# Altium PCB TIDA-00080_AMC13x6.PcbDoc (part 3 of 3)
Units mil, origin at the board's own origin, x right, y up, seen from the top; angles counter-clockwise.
Board outline 7283.46 x 2559.06 mil, 4 copper layers (Top Layer, MidLayer1, MidLayer2, Bottom Layer), stack 61.2 mil thick; 372 components, 160 nets, 901 pads, 256 vias.
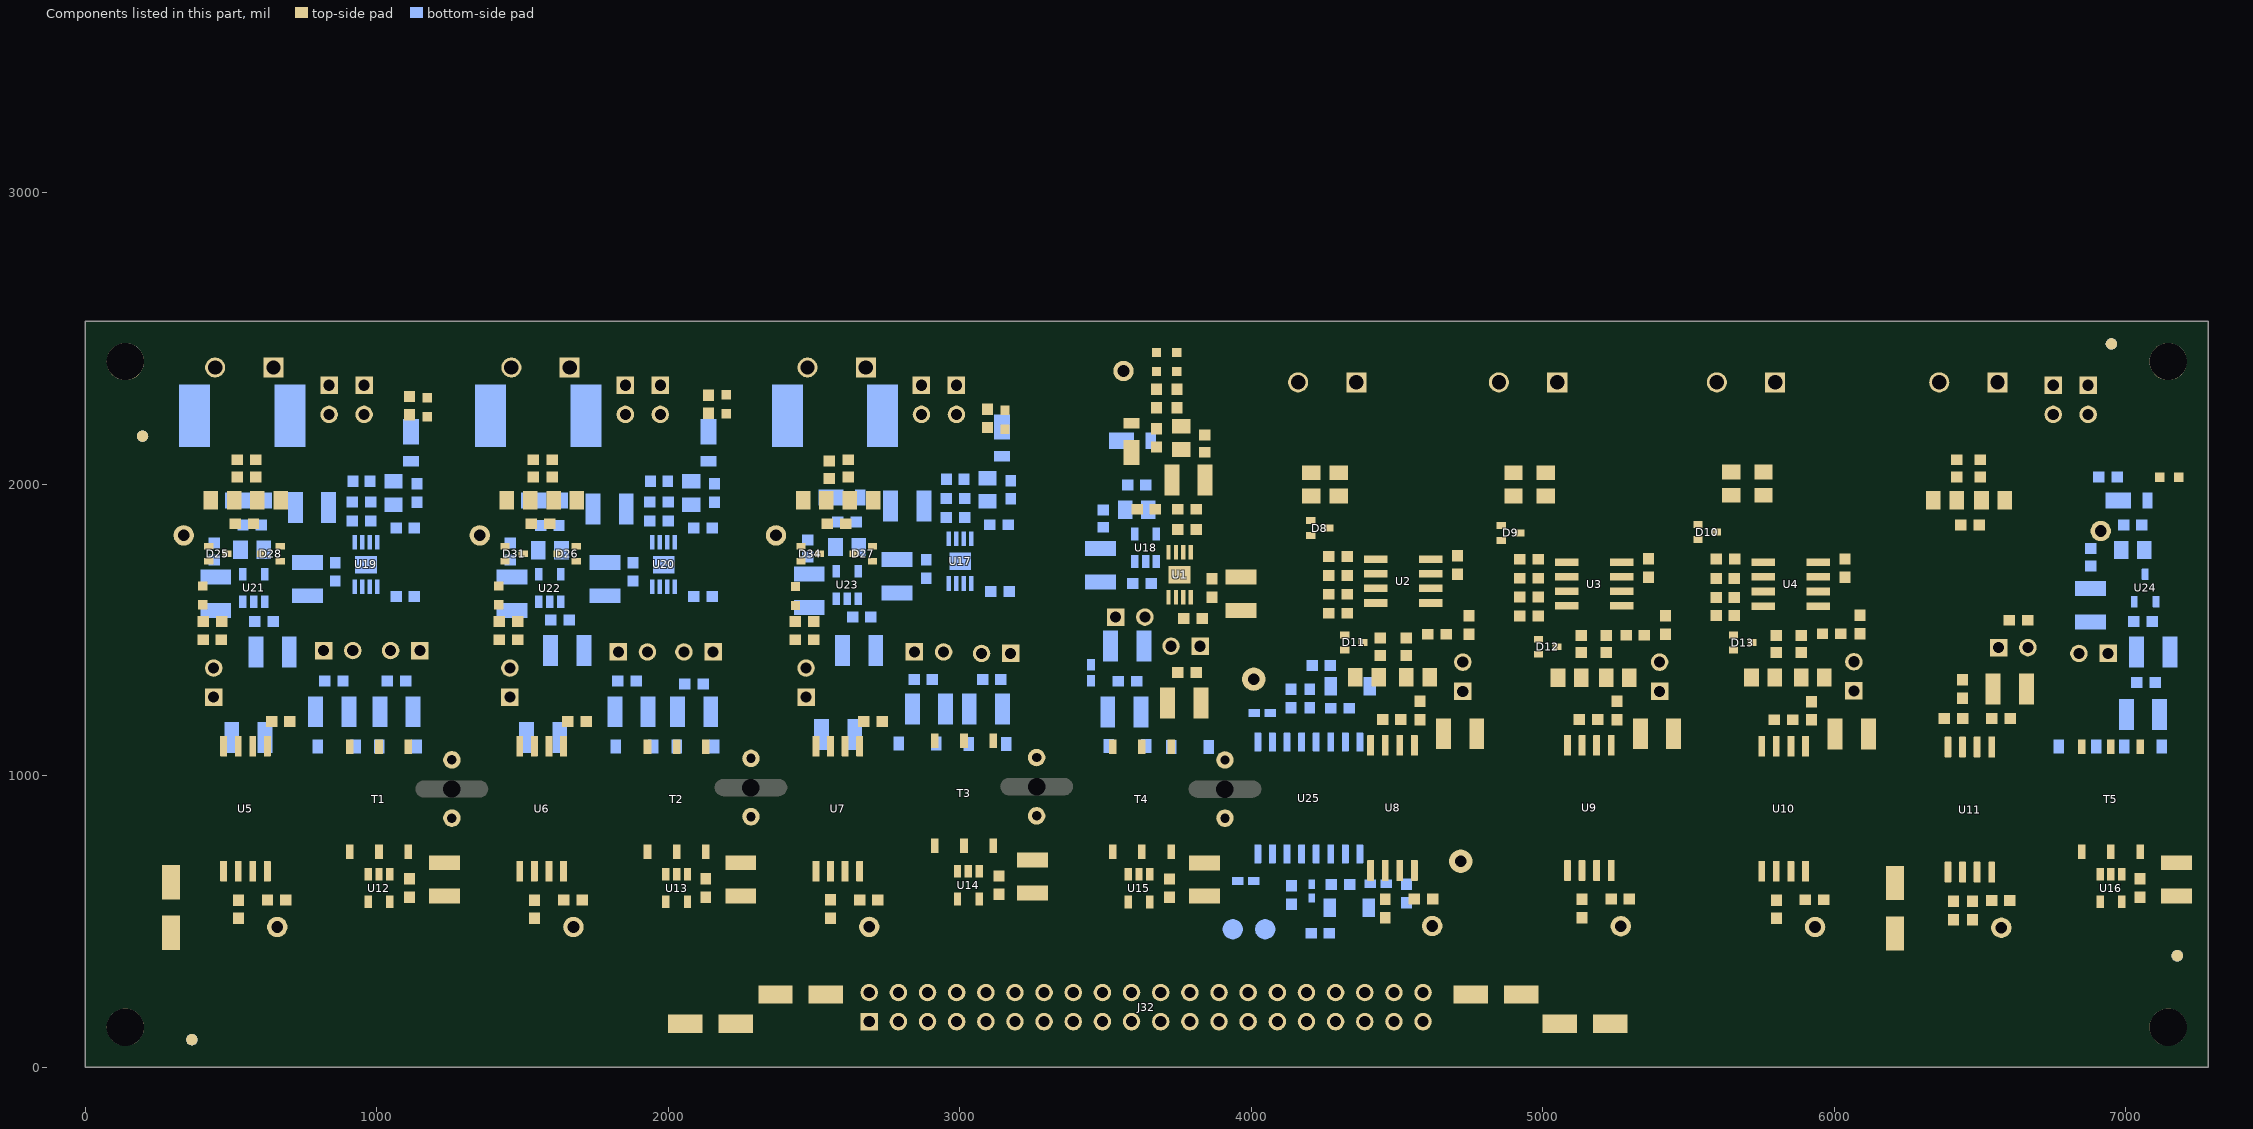
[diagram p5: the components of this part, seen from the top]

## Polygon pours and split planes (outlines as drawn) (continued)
GND_WSH1 on MidLayer2 "g" (solid, remove dead copper, pour order 193): 3214,2500 2851,2500 2841,2490 2838,2487 2838,2366 2838,2101 2817,2080 2362,2080 2338,2056 2328,2046 2328,1815 2328,1311 2420,1219 2434.99,1204.01 2434.99,1170 2434.99,1079 2443.99,1070 3100,1070 3245,1215 3245,2469
-5.0V_PH on MidLayer2 "g" (solid, remove dead copper, pour order 191): 6190,1095 6158.5,1063.5 3552.99,1063.5 3475.2,1141.3 3430.2,1186.3 3430.2,1844.72 3430.2,2476.2 3454,2500 3802,2500 3813,2489 3832,2470 3832,2370 3832,2290 3856,2266 4125,1997 6155,1997 6190.17,1961.84
+5.0V_VDC on MidLayer2 "g" (solid, remove dead copper, pour order 183): 6340,1997 7169,1997 7215,1951 7215,1095 7183.5,1063.5 6360.5,1063.5 6330,1094 6306.45,1117.55 6306.45,1905 6306.45,1963.45
DGND on MidLayer2 "g" (solid, remove dead copper, pour order 177): 45,554.53 45,762 67,784 7211,784 7234,761 7234,92 7188,46 93,46 46,93 45,94 45,550.05
+5.0V_PH on Bottom Layer "g" (solid, remove dead copper, pour order 179): 3582,2330 3792,2330 3856,2266 4125,1997 6155,1997 6190,1962 6190,1137 6190,1095 6165,1070 6158.5,1063.5 6020.5,1063.5 4234.5,1063.5 4114,1184 4038,1260 4038,1560 4038,1802 3737,2103 3737,2147 3737,2183 3710,2210 3614,2210 3597,2193 3597,1884 3592,1879 3541.08,1879 3527.6,1892.48 3467.6,1892.48 3457.6,1902.48 3457.6,2292.6 3495,2330
+5V_CNTL on Bottom Layer "g" (solid, remove dead copper, pour order 175): 45,554.53 45,762 67,784 7211,784 7234,761 7234,92 7188,46 93,46 46,93 45,94 45,550.05
NetC134_1 on Bottom Layer "vdd" (solid, remove dead copper, pour order 229): 3444,1350 3565.6,1350 3567.6,1348 3567.6,1301.6 3543,1277 3543,1082 3529,1068 3488.89,1068 3472.89,1084 3472.89,1143.61 3430.2,1186.3 3430.2,1347.17 3433,1349.97
+6V_PH on Bottom Layer "vdd" (solid, remove dead copper, pour order 227): 3446,1577 3430.2,1561.2 3430.2,1361.82 3433,1359.02 3469.02,1359.02 3488.84,1378.84 3561.84,1378.84 3569,1386 3569,1572 3564,1577
GND_XSH1 on Bottom Layer "g" (solid, remove dead copper, pour order 213): 6780,2370 6724,2370 6721,2367 6721,2047 6671,1997 6340,1997 6322,1979 6306.45,1963.45 6306.45,1117.55 6360.5,1063.5 6728.21,1063.5 6744.58,1079.87 6744.58,1625.58 6791,1672 6800,1681 6800,2232 6800,2359 6789,2370
GND_VDC on Bottom Layer "g" (solid, remove dead copper, pour order 181): 6836,2365 6836,2219 6970,2085 7049,2006 7049,1735.45 7054.45,1730 7089.45,1730 7099.45,1720 7099.45,1660 7084.45,1645 7059.45,1645 7054.45,1640 7054.45,1575 7069.45,1560 7069.45,1510 7094.45,1485 7094.45,1152.55 7103,1144 7214,1144 7227,1157 7236,1166 7236,2078 7100,2214 6944,2370 6841,2370
NetC48_1 on Bottom Layer "g" (solid, remove dead copper, pour order 161): 2601.99,1265 2561.99,1305 2441.99,1305 2434.99,1298 2434.99,1230 2439.99,1225 2550.99,1225 2599.99,1176 2599.99,1077 2606.99,1070 2689.99,1070 2694.99,1075 2694.99,1246 2694.99,1259 2688.99,1265
GND_WSH1 on Bottom Layer "g" (solid, remove dead copper, pour order 163): 2564.99,1184 2564.99,1079 2558.99,1073 2555.99,1070 2549.99,1070 2443.99,1070 2434.99,1079 2434.99,1188 2441.99,1195 2558.99,1195 2564.99,1189
-6V_WSH on Bottom Layer "g" (solid, remove dead copper, pour order 159): 2953,1700 2862,1700 2832,1670 2742,1670 2727,1655 2727,1595 2807,1515 3112,1515 3137,1490 3137,1395 3112,1370 3112,1095 3127,1080 3172,1080 3197,1105 3197,1360 3222,1385 3222,1525 3182,1565 2993,1565 2967,1591 2967,1685 2965.1,1686.9 2952,1700 2948.3,1700
-6V_VSH on Bottom Layer "g" (solid, remove dead copper, pour order 157): 1940,1690 1849,1690 1819,1660 1729,1660 1714,1645 1714,1585 1794,1505 2099,1505 2124,1480 2124,1385 2099,1360 2099,1085 2114,1070 2169,1070 2184,1085 2184,1350 2209,1375 2209,1515 2169,1555 1980,1555 1954,1581 1954,1675 1952.1,1676.9 1939,1690 1935.3,1690
-6V_USH on Bottom Layer "g" (solid, remove dead copper, pour order 155): 919,1690 828,1690 798,1660 708,1660 693,1645 693,1585 773,1505 1078,1505 1103,1480 1103,1385 1078,1360 1078,1085 1093,1070 1148,1070 1163,1085 1163,1350 1188,1375 1188,1515 1148,1555 959,1555 933,1581 933,1675 931.1,1676.9 918,1690 914.3,1690
NetC91_2 on Bottom Layer "g" (solid, remove dead copper, pour order 153): 2975.4,1787 2948.4,1787 2935.4,1800 2875.4,1800 2850.4,1825 2850.4,1976 2861.4,1987 2921.4,1987 2929.4,1995 2929.4,2037 2937.4,2045 2976.4,2045 2979.4,2042 2979.4,1864 2975.4,1860
-5.0V_WSH on Bottom Layer "g" (solid, remove dead copper, pour order 151): 2995.39,1990.78 2995.39,2095.78 3010.39,2110.78 3080.39,2110.78 3184.39,2110.78 3198.03,2097.14 3198.03,1990.78
GND_WSH on Bottom Layer "Bottom Layer-No Net 1" (solid, remove dead copper, pour order 149): 2690,1375 2751.2,1375 2755,1380 2755,1509.98 2700,1564.98 2700,1685 2720,1705 3090,1705 3100,1715 3215,1715 3255,1755 3255,1930 3225,1960 3070,1960 3060,1950 3060,1915 3075,1900 3140,1900 3150,1890 3150,1820 3145,1815 3075,1815 3055,1835 3005,1835 3005,1775 2990,1760 2835,1760 2805,1790 2805,1961 2791,1975 2685,1975 2635,1975 2625,1965 2625,1640 2635,1630 2635,1575 2660,1550 2660,1405
+5.0V_WSH on Bottom Layer "g" (solid, remove dead copper, pour order 145): 2444,1933 2502,1991 2596,1991 2606,1981 2606,1756 2559,1756 2521,1794 2519,1796 2459,1796 2444,1811
NetC84_2 on Bottom Layer "g" (solid, remove dead copper, pour order 143): 2970,1777 2943,1777 2930,1790 2870,1790 2845,1815 2845,1966 2856,1977 2916,1977 2924,1985 2924,2027 2932,2035 2971,2035 2974,2032 2974,1854 2970,1850
NetC18_2 on Bottom Layer "g" (solid, remove dead copper, pour order 135): 1586,1265 1546,1305 1426,1305 1419,1298 1419,1230 1424,1225 1535,1225 1584,1176 1584,1077 1591,1070 1674,1070 1679,1075 1679,1246 1679,1259 1673,1265
GND_VSH1 on Bottom Layer "g" (solid, remove dead copper, pour order 133): 1549,1184 1549,1079 1543,1073 1540,1070 1534,1070 1428,1070 1419,1079 1419,1188 1426,1195 1543,1195 1549,1189
NetC91_2 on Bottom Layer "g" (solid, remove dead copper, pour order 131): 1954,1777 1927,1777 1914,1790 1854,1790 1829,1815 1829,1966 1840,1977 1900,1977 1908,1985 1908,2027 1916,2035 1955,2035 1958,2032 1958,1854 1954,1850
+5.0V_VSH on Bottom Layer "g" (solid, remove dead copper, pour order 129): 1409,1954.18 1429,1974.18 1579,1974.18 1588,1965.18 1588,1745.18 1582,1739.18 1524,1739.18 1486,1777.18 1484,1779.18 1424,1779.18 1409,1794.18 1409,1954.18
-5.0V_VSH on Bottom Layer "g" (solid, remove dead copper, pour order 127): 1979,1979.18 1979,2084.18 1994,2099.18 2064,2099.18 2168,2099.18 2181.63,2085.54 2181.63,1979.18
GND_USH1 on Bottom Layer "g" (solid, remove dead copper, pour order 119): 533,1184 533,1079 527,1073 524,1070 518,1070 412,1070 403,1079 403,1188 410,1195 527,1195 533,1189
NetC17_2 on Bottom Layer "g" (solid, remove dead copper, pour order 117): 570,1265 530,1305 410,1305 403,1298 403,1230 408,1225 519,1225 568,1176 568,1077 575,1070 658,1070 663,1075 663,1246 663,1259 657,1265
-5.0V_USH on Bottom Layer "g" (solid, remove dead copper, pour order 113): 958,1980 958,2085 973,2100 1043,2100 1147,2100 1160.64,2086.36 1160.64,1980
NetC88_2 on Bottom Layer "g" (solid, remove dead copper, pour order 111): 933,1777 906,1777 893,1790 833,1790 808,1815 808,1966 819,1977 879,1977 887,1985 887,2027 895,2035 934,2035 937,2032 937,1854 933,1850
+5.0V_USH on Bottom Layer "g" (solid, remove dead copper, pour order 109): 388,1955 408,1975 558,1975 567,1966 567,1746 561,1740 503,1740 465,1778 463,1780 403,1780 388,1795 388,1955
GND_VSH on Bottom Layer "Bottom Layer-No Net 1" (solid, remove dead copper, pour order 56): 1899,1165 2059,1165 2084,1185 2084,1445 2064,1465 1914,1465 1899,1450 1899,1380 1869,1345 1869,1195
GND_VSH on Bottom Layer "Bottom Layer-No Net 1" (solid, remove dead copper, pour order 61): 1674,1375 1735.2,1375 1739,1380 1739,1509.98 1684,1564.98 1684,1685 1704,1705 2074,1705 2084,1715 2199,1715 2239,1755 2239,1930 2209,1960 2054,1960 2044,1950 2044,1915 2059,1900 2124,1900 2134,1890 2134,1820 2129,1815 2059,1815 2039,1835 1989,1835 1989,1775 1974,1760 1819,1760 1789,1790 1789,1961 1775,1975 1669,1975 1619,1975 1609,1965 1609,1640 1619,1630 1619,1575 1644,1550 1644,1405
GND_USH on Bottom Layer "Bottom Layer-No Net 1" (solid, remove dead copper, pour order 63): 878,1165 1038,1165 1058,1185 1058,1370 1083,1395 1083,1470 1073,1480 898,1480 873,1470 873,1375 863,1350 863,1180
GND_PH on Bottom Layer "Bottom Layer-No Net 1" (solid, remove dead copper, pour order 77): 3430.2,1689.72 3540.2,1689.72 3555.2,1674.72 3555.2,1619.72 3535.2,1599.72 3430.2,1599.72
+5.0V_VDC on Bottom Layer "Bottom Layer-No Net 4" (solid, pour order 57): 6929.45,2050 6929.45,1995 6999.45,1995 7019.45,1975 7019.45,1755 7004.45,1740 6939.45,1740 6919.45,1760 6859.45,1760 6859.45,2035 6874.45,2050
NetC123_2 on Bottom Layer "Bottom Layer-No Net 4" (solid, pour order 66): 6934.45,1680 6934.45,1610 6929.45,1615 6824.45,1615 6824.45,1720 6844.45,1740 6909.45,1740 6934.45,1715
GND_PH on Bottom Layer "Bottom Layer-No Net 1" (solid, remove dead copper, pour order 71): 3615.2,1164.72 3715.2,1164.72 3755.2,1204.72 3755.2,1459.72 3690.2,1509.72 3690.2,1574.72 3605.2,1574.72 3605.2,1179.72
+6V_VDC on Bottom Layer "Bottom Layer-No Net 1" (solid, remove dead copper, pour order 60): 6874.45,1075 7014.45,1075 7044.45,1105 7044.45,1270 7059.45,1285 7064.45,1290 7064.45,1465 7064.45,1485 7049.45,1500 7049.45,1550 7044.45,1555 7009.45,1555 7004.45,1555 6999.45,1550 6999.45,1510 6999.45,1485 6979.45,1465 6974.45,1460 6914.45,1460 6909.45,1460 6899.45,1450 6894.45,1445 6894.45,1380 6894.45,1180 6874.45,1160 6869.45,1155 6869.45,1085 6869.45,1080 6874.45,1075
GND_VDC on Bottom Layer "Bottom Layer-No Net 1" (solid, remove dead copper, pour order 64): 6814.45,1570 6919.45,1570 6934.45,1555 6934.45,1510 6924.45,1500 6884.45,1500 6869.45,1485 6869.45,1390 6869.45,1375 6844.45,1350 6779.45,1350 6769.45,1350 6749.45,1370 6749.45,1555 6764.45,1570 6819.45,1570
-6V_PH on Bottom Layer "Bottom Layer-No Net 1" (solid, remove dead copper, pour order 62): 3800.2,1077.22 3870.2,1077.22 3875.2,1082.22 3875.2,1087.22 3875.2,1182.22 3875.2,1407.22 3875.2,1477.22 3850.2,1502.22 3800.2,1502.22 3790.2,1492.22 3790.2,1432.22 3790.2,1087.22 3800.2,1077.22
GND_PH on Bottom Layer "Bottom Layer-No Net 2" (solid, pour order 86): 3715.2,1669.72 3730.2,1654.72 3885.2,1654.72 3905.2,1674.72 3905.2,1819.72 3695.2,2054.72 3695.2,2194.72 3610.2,2189.72 3610.2,2004.72 3625.2,1984.72 3625.2,1739.72 3695.2,1739.72 3715.2,1719.72
GND_WSH on Bottom Layer "Bottom Layer-No Net 1" (solid, remove dead copper, pour order 88): 2925,1175 3060,1175 3100,1215 3100,1455 2935,1455 2895,1415 2895,1205
+6V_USH on Bottom Layer "Bottom Layer-No Net 1" (solid, remove dead copper, pour order 68): 753,1075 813,1075 818,1075 828,1085 838,1095 838,1230 838,1475 783,1475 778,1475 768,1465 758,1455 758,1385 758,1350 753,1345 718,1345 653,1345 623,1375 608,1390 608,1505 608,1540 588,1560 588,1610 588,1615 583,1620 564.65,1620 564.65,1581.65 563,1580 563,1560 563,1555 533,1525 518,1510 518,1375 518,1365 563,1320 603,1280 653,1280 729,1280 743,1266 743,1105 743,1085
GND_USH on Bottom Layer "Bottom Layer-No Net 1" (solid, remove dead copper, pour order 70): 663,1365 664.72,1363.28 734.2,1363.28 734.2,1486.72 733,1487.92 733,1505 733,1510 673,1570 668,1575 668,1605 668,1660 703,1695 713,1705 868,1705 918,1705 928,1695 933,1690 998,1690 1038,1690 1073,1725 1153,1725 1168,1725 1190,1747 1190,1953 1178,1965 1068,1965 1028,1965 1023,1960 1018,1955 1018,1920 1018,1911 1033,1896 1098,1896 1102,1896 1108,1890 1113,1885 1113,1840 1113,1830 1093,1810 1088,1805 1033,1805 1013,1825 973,1825 968,1820 968,1775 968,1770 963,1765 878,1765 813,1765 778,1800 773,1805 773,1965 758,1980 601,1980 583,1962 583,1830 583,1745 598,1730 603,1725 623,1725 628,1725 638,1715 639.03,1713.97 639.03,1635.16 638.16,1635.16 633,1630 613,1630 608,1630 606.29,1628.29 606.29,1620 606.29,1581.71 608,1580 628,1560 628,1520 628,1400
+6V_WSH on Bottom Layer "Bottom Layer-No Net 1" (solid, remove dead copper, pour order 52): 2771,1085 2835,1085 2835,1090 2860,1115 2865,1120 2865,1330 2865,1445 2845,1465 2795,1465 2785,1465 2775,1455 2775,1365 2765,1355 2665,1355 2660,1355 2645,1370 2630,1385 2630,1555 2620,1565 2615,1570 2610,1570 2605,1575 2605,1615 2605,1620 2600,1625 2590,1625 2585,1620 2585,1585 2585,1570 2575,1560 2575,1500 2575,1310 2593,1292 2758,1292 2771,1279
NetD35_2 on Bottom Layer "Bottom Layer-No Net" (solid, remove dead copper, pour order 51): 2895,1150 3040,1150 3060,1150 3070,1140 3075,1135 3075,1105 3075,1090 3065,1080 2925,1080 2890,1080 2885,1085 2885,1140 2885,1145 2890,1150 2895,1150
+6V_VSH on Bottom Layer "Bottom Layer-No Net 1" (solid, remove dead copper, pour order 55): 1779,1065 1834,1065 1844,1075 1844,1375 1864,1395 1864,1460 1779,1460 1764,1440 1764,1355 1754,1345 1659,1345 1619,1385 1619,1555 1604,1570 1604,1615 1584,1615 1584,1575 1529,1520 1529,1375 1629,1275 1709,1275 1764,1235 1764,1085
GND_USH1 on Bottom Layer "g" (solid, remove dead copper, pour order 215): 321,2180 321,2402 348,2429 359,2440 446,2440 469,2440 481,2428 481,2140 469,2128 325,2128 321,2132
NetFB2_1 on Bottom Layer "g" (solid, remove dead copper, pour order 217): 608,2400 608,2134 615,2127 754,2127 757,2130 757,2434 751,2440 613,2440 608,2435
NetFB4_1 on Bottom Layer "g" (solid, remove dead copper, pour order 219): 1624,2400 1624,2134 1631,2127 1770,2127 1773,2130 1773,2434 1767,2440 1629,2440 1624,2435
GND_VSH1 on Bottom Layer "g" (solid, remove dead copper, pour order 221): 1337,2180 1337,2402 1364,2429 1375,2440 1462,2440 1485,2440 1497,2428 1497,2140 1485,2128 1341,2128 1337,2132
NetFB7_1 on Bottom Layer "g" (solid, remove dead copper, pour order 223): 2639.99,2400 2639.99,2134 2646.99,2127 2785.99,2127 2788.99,2130 2788.99,2434 2782.99,2440 2644.99,2440 2639.99,2435
GND_WSH1 on Bottom Layer "g" (solid, remove dead copper, pour order 225): 2352.99,2180 2352.99,2402 2379.99,2429 2390.99,2440 2477.99,2440 2500.99,2440 2512.99,2428 2512.99,2140 2500.99,2128 2356.99,2128 2352.99,2132
GND_WSH on Top Layer "g" (solid, remove dead copper, pour order 171): 3285,1030 3160,1030 3105,1085 3105,1155 2920,1340 2913,1347 2913,1431 2913,1453 2929,1469 3088,1469 3105,1452 3105,1360 3105,1355 3245,1215 3301,1159 3301,1046
GND_VSH on Top Layer "g" (solid, remove dead copper, pour order 169): 2295,1023 2165,1023 2099,1089 2099,1159 1914,1344 1897,1361 1897,1447 1923,1473 2082,1473 2099,1456 2099,1364 2099,1359 2239,1219 2315,1143 2315,1069 2315,1035 2303,1023
GND_WSH1 on Top Layer "g" (solid, remove dead copper, pour order 167): 2443.99,1070 2434.99,1079 2434.99,1170 2441.99,1177 2509.99,1177 2516.99,1170 2518.99,1168 2518.99,1132 2518.99,1077 2511.99,1070
NetC48_1 on Top Layer "g" (solid, remove dead copper, pour order 165): 2641.99,1103 2641.99,1163 2621.99,1183 2621.99,1256 2630.99,1265 2688.99,1265 2694.99,1259 2694.99,1072 2688.99,1066 2647.99,1066 2641.99,1072
NetC18_2 on Top Layer "g" (solid, remove dead copper, pour order 139): 1626,1103 1626,1163 1606,1183 1606,1256 1615,1265 1673,1265 1679,1259 1679,1072 1673,1066 1632,1066 1626,1072
GND_VSH1 on Top Layer "g" (solid, remove dead copper, pour order 137): 1428,1070 1419,1079 1419,1170 1426,1177 1494,1177 1501,1170 1503,1168 1503,1132 1503,1077 1496,1070
DGND on Top Layer "g" (solid, remove dead copper, pour order 125): 465,708.5 257,708.5 243,694.5 243,580.5 252,571.5 483,571.5 490,578.5 490,698.5 479,709.5
GND_USH on Top Layer "g" (solid, remove dead copper, pour order 123): 1274,1024 1144,1024 1078,1090 1078,1160 893,1345 886,1352 886,1436 886,1458 902,1474 1061,1474 1078,1457 1078,1365 1078,1360 1218,1220 1294,1144 1294,1070 1294,1036 1282,1024
GND_USH1 on Top Layer "g" (solid, remove dead copper, pour order 121): 412,1070 403,1079 403,1170 410,1177 478,1177 485,1170 487,1168 487,1132 487,1077 480,1070
NetC17_2 on Top Layer "g" (solid, remove dead copper, pour order 115): 610,1103 610,1163 590,1183 590,1256 599,1265 657,1265 663,1259 663,1072 657,1066 616,1066 610,1072
NetC50_1 on Top Layer "g" (solid, remove dead copper, pour order 107): 4754.89,1325.51 4680.89,1325.51 4674.89,1319.51 4674.89,1263.51 4629.89,1218.51 4560.89,1218.51 4553.62,1211.25 4553.62,1192.51 4553.62,1156.25 4543.89,1146.51 4543.89,1070.51 4547.89,1066.51 4678.89,1066.51 4685.89,1073.51 4687.89,1075.51 4687.89,1129.51 4687.89,1189.51 4726.89,1228.51 4759.89,1261.51 4759.89,1269.51 4759.89,1322.51 4756.89,1325.51
NetC52_1 on Top Layer "g" (solid, remove dead copper, pour order 105): 5430.19,1325.51 5356.19,1325.51 5350.19,1319.51 5350.19,1263.51 5305.19,1218.51 5236.19,1218.51 5228.93,1211.25 5228.93,1192.51 5228.93,1156.25 5219.19,1146.51 5219.19,1070.51 5223.19,1066.51 5354.19,1066.51 5361.19,1073.51 5363.19,1075.51 5363.19,1129.51 5363.19,1189.51 5402.19,1228.51 5435.19,1261.51 5435.19,1269.51 5435.19,1322.51 5432.19,1325.51
DGND on Top Layer "g" (solid, remove dead copper, pour order 101): 6379.45,706 6171.45,706 6157.45,692 6157.45,578 6166.45,569 6340,569 6404.45,633.45 6404.45,696 6393.45,707
NetC19_2 on Top Layer "g" (solid, remove dead copper, pour order 99): 6516.45,1194 6516.45,1461 6532.45,1477 6592.45,1477 6598.45,1471 6598.45,1379 6580.45,1361 6580.45,1251 6567.45,1238 6563.45,1234 6563.45,1143 6563.45,1068 6556.45,1061 6522.45,1061 6516.45,1067
GND_PH on Top Layer "Top Layer-No Net" (solid, pour order 79): 3795.2,2144.72 3785.2,2154.72 3560.2,2154.72 3560.2,1779.72 3580.2,1754.72 3580.2,1214.72 3770.2,1214.72 3770.2,1474.72 3740.2,1504.72 3710.2,1504.72 3695.2,1519.72 3695.2,1649.72 4020.2,1649.72 4020.2,1729.72 3775.2,1729.72 3775.2,2065.72 3795.2,2085.72
-6V_PH on Top Layer "Bottom Layer-No Net 1" (solid, remove dead copper, pour order 58): 3800.2,1409.72 3790.2,1419.72 3790.2,1499.72 3895.2,1499.72 3915.2,1514.72 3915.2,1564.72 3912.42,1564.72 3892.4,1584.74 3785.2,1584.72 3785.2,1629.72 3995.2,1629.72 4020.2,1604.72 4020.2,1484.72 3935.2,1409.72
NetC54_1 on Top Layer "g" (solid, remove dead copper, pour order 103): 6096.5,1322.5 6022.5,1322.5 6016.5,1316.5 6016.5,1260.5 5971.5,1215.5 5902.5,1215.5 5895.24,1208.24 5895.24,1189.5 5895.24,1153.24 5885.5,1143.5 5885.5,1067.5 5889.5,1063.5 6020.5,1063.5 6027.5,1070.5 6029.5,1072.5 6029.5,1126.5 6029.5,1186.5 6068.5,1225.5 6101.5,1258.5 6101.5,1266.5 6101.5,1319.5 6098.5,1322.5

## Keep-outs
Keep-Out Layer:
  circle w8: c7736.22,2421.26 r118.11
  circle w8: c137.8,2421.26 r118.11
  circle w8: c137.8,137.8 r118.11
  circle w8: c7736.22,137.8 r118.11
  lines w10: -5,0 -5,3450 ; 0,-5 4950,-5

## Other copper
Top Layer:
  region net NetD35_2: 2990,1085 2980,1075 2905,1075 2895,1085 2895,1145 2905,1155 2980,1155 2990,1145
  region net NetD32_2: 2004,1070 1994,1060 1919,1060 1909,1070 1909,1130 1919,1140 1994,1140 2004,1130
  region net NetD29_2: 983,1070 973,1060 898,1060 888,1070 888,1130 898,1140 973,1140 983,1130
  region net -5.0V_PH: 3820.2,2149.72 3860.2,2149.72 3870.2,2159.72 3870.2,2179.72 3820.2,2229.72 3720.2,2229.72 3710.2,2239.72 3710.2,2274.72 3700.2,2284.72 3655.2,2284.72 3615.2,2324.72 3575.2,2324.72 3560.2,2309.72 3560.2,2189.72 3580.2,2169.72 3800.2,2169.72
  region net NetC9_2: 3785.2,1739.72 3785.2,2059.72 3810.2,2084.72 3810.2,2119.72 3820.2,2129.72 3860.2,2129.72 3870.2,2119.72 3870.2,1754.72 3855.2,1739.72
  region net NetD37_2: 3659,1058 3670.2,1049.72 3685.2,1049.72 3699,1058 3699,1168 3679,1188 3539,1188 3514,1163 3514,1058 3564,1058 3564,1134.57 3654,1134.57 3659,1113
  region net -6V_PH: 3790.2,1499.72 3790.2,1214.72 3795.2,1189.72 3860.2,1189.72 3860.2,1490.92 3851.4,1499.72
  text ".Layer_Name" at 577,-858.49 h60
MidLayer1:
  pour cut-out: 7084.67,246.8 7044.67,206.8 7044.67,36.33 7068,13 7224.67,13 7224.67,61.8 7259.67,96.8 7254.67,101.8 7254.67,206.8 7214.67,246.8
  pour cut-out: 40,288 252,288 271.36,268.64 271.36,60.36 246,35 70,35 70,45 40,75
  text ".Layer_Name" at 577,-858.49 h60
MidLayer2:
  pour cut-out: 40,288 252,288 271.36,268.64 271.36,60.36 246,35 70,35 70,45 40,75
  pour cut-out: 7084.67,246.8 7044.67,206.8 7044.67,36.33 7068,13 7224.67,13 7224.67,61.8 7259.67,96.8 7254.67,101.8 7254.67,206.8 7214.67,246.8
  text ".Layer_Name" at 577,-858.49 h60
Bottom Layer:
  pour cut-out: 3997,783 4004.26,775.74 4388.27,775.74 4388.27,789.73 4384,794 3998,794
  region net NetC111_2: 3467.6,1872.48 3430.2,1844.72 3430.2,1739.72 3462.6,1712.48 3612.6,1712.48 3612.6,1757.48 3512.6,1857.48 3512.6,1872.48
  pour cut-out: 40,288 252,288 271.36,268.64 271.36,60.36 246,35 70,35 70,45 40,75
  pour cut-out: 7084.67,246.8 7044.67,206.8 7044.67,36.33 7068,13 7224.67,13 7224.67,61.8 7259.67,96.8 7254.67,101.8 7254.67,206.8 7214.67,246.8
  region net NetC121_2: 2498.99,1770.26 2548.99,1720.26 2548.99,1675.26 2588.99,1635.26 2588.99,1585.26 2563.99,1585.26 2563.99,1615.26 2548.99,1630.26 2433.99,1630.26 2423.99,1640.26 2423.99,1755.26 2438.99,1770.26
  region net NetC117_2: 1479,1759.5 1529,1709.5 1529,1664.5 1569,1624.5 1569,1574.5 1544,1574.5 1544,1604.5 1529,1619.5 1414,1619.5 1404,1629.5 1404,1744.5 1419,1759.5
  region net NetC113_2: 463,1760 513,1710 513,1665 553,1625 553,1575 528,1575 528,1605 513,1620 398,1620 388,1630 388,1745 403,1760
  pour cut-out: 2646.49,1630.27 2646.49,1671.97 2648.2,1720.27 2628.2,1740.27 2563.2,1740.27 2563.2,1630.27
  pour cut-out: 606.29,1620 606.29,1661.71 608,1710 588,1730 523,1730 523,1620
  region net NetD37_2: 3740.2,1129.72 3740.2,1069.72 3730.2,1059.72 3630.2,1059.72 3620.2,1069.72 3620.2,1129.72 3630.2,1139.72 3730.2,1139.72
  region net NetD32_2: 2049,1130 2049,1070 2039,1060 1939,1060 1929,1070 1929,1130 1939,1140 2039,1140
  region net NetD29_2: 1028,1130 1028,1070 1018,1060 918,1060 908,1070 908,1130 918,1140 1018,1140
  text ".Layer_Name" at 577,-858.49 h60

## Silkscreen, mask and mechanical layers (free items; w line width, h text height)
Top Overlay:
  lines w6: 2486,1641 2498,1641 ; 2497,1612 2497,1624 ; 2498,1660 2498,1641 ; 2509,1641 2498,1641 ; 3686.1,1610.62 3686.1,1766.22 ; 3821.1,1610.62 3821.1,1766.22 ; 3878,1707 3878,1718 ; 4427.38,1558.01 4617.38,1558.01 ; 4427.38,1773.01 4617.38,1773.01 ; 4437.38,1274.01 4445.38,1282.01 4482.38,1282.01 4498.38,1298.01 ; 4697.36,1513.21 4697.36,1530.99 ; 5082.69,1548.01 5272.69,1548.01 ; 5082.69,1763.01 5272.69,1763.01 ; 5122.69,1277.01 5131.69,1286.01 5172.69,1286.01 5183.69,1297.01 ; 5756.5,1547.5 5946.5,1547.5 ; 5756.5,1762.5 5946.5,1762.5 ; 5782,1275 5792,1285 5840,1285 5852.5,1297.5 ; 2498,1641 2514,1625 2514,1624 2513,1624 2481,1624 2498,1641
  lines w10: 2624.73,97.19 4654.73,97.19 ; 2624.73,-2.81 4654.73,-2.81 4654.73,297.99 4652.72,300 2789.72,300 2624.73,300 2624.73,-2.81
  text "40" at 4566,316 h35
  text "2" at 2679,315 h35
  text "-" at 6818.95,281 h60
  text "'.PCB_Rev'" at 6883.95,280 h60
  text "'.PRJ_Number'" at 5749,279 h60
  text "39" at 4673,114 h35
  text "1" at 2596,112 h35
  text ".Layer_Name" at 577,-858.49 h60
Bottom Overlay:
  lines w6: 849,1843 853.8,1847.8 888.02,1847.8 ; 852,2030 852,2026 888.02,1989.98 888.02,1967.27 ; 893,1650 893,1805 ; 1033,1650 1033,1805 ; 1692,1522 1745.2,1522 ; 1869,1836 1879,1846 1907.22,1846 1909.02,1847.8 ; 1878,2014 1909.02,1982.98 1909.02,1967.27 ; 1914,1650 1914,1805 ; 2054,1650 2054,1805 ; 2733,1543 2744,1543 ; 2875,1844 2888,1857 2934,1857 ; 2897,2021 2925.41,1992.59 2925.41,1978.87 ; 2912.66,1650.02 2912.66,1637.34 2918,1632 ; 4156,1358 4156,1348 4172.46,1331.54 4172.46,1326.02 ; 4365.98,655.27 4365.98,662.98 4380,677 4397,677 4418,698
  text ".Layer_Name" at 577,-858.49 h60
Top Paste:
  text ".Layer_Name" at 577,-858.49 h60
Bottom Paste:
  text ".Layer_Name" at 577,-858.49 h60
Top Solder:
  text ".Layer_Name" at 577,-858.49 h60
  text ".Layer_Name" at 577,-858.49 h60
Bottom Solder:
  text ".Layer_Name" at 577,-858.49 h60
Drill Guide:
  text ".Layer_Name" at 577,-858.49 h60
M1 Board Outline:
  the board outline again, w10
M2 Board Dimensions:
  rectangle: 124.5,-410.5 499.5,-285.5
  rectangle: -0.5,-285.5 124.5,-160.5
  lines w7: -0.5,-285.5 999.5,-285.5 ; 124.5,-410.5 124.5,-160.5 ; 249.5,-410.5 249.5,-160.5 ; 499.5,-410.5 499.5,-160.5 ; 749.5,-410.5 749.5,-160.5 ; -0.5,-410.5 -0.5,-160.5 999.5,-160.5 999.5,-410.5 -0.5,-410.5
  lines w10: -0.5,-475.5 -0.5,-455.5 ; 59.5,-485.5 -0.5,-465.5 ; 59.5,-445.5 -0.5,-465.5 ; 223.58,-465.5 -0.5,-465.5 ; 775.42,-465.5 999.5,-465.5 ; 939.5,-485.5 999.5,-465.5 ; 939.5,-445.5 999.5,-465.5 ; 999.5,-475.5 999.5,-455.5
  text "1000 (mil)" at 233.58,-501.49 h60
M3 3D STEP Top:
  text ".Layer_Name" at 577,-858.49 h60
M4 3D STEP Bottom:
  text ".Layer_Name" at 577,-858.49 h60
M5 Assembly Top:
  circle w10: c2869,2411 r6.71
  circle w6: c2893.82,150 r11.18
  circle w10: c6752,2422 r7.07
  lines w10: -292,-930.17 6308,-930.17 ; -292,-726.83 6310,-726.83 ; -292,-523.5 -292,-1133.5 3713,-1133.5 6310,-1133.5 6310,-523.5 -291.5,-523.5 -291.5,-1133.5 1284,-1133.5 ; 2173,-1133.5 2173,-523.5 ; 3440,-726.83 3440,-523.5 ; 4280,-726.83 4280,-523.5 ; 4902,-1140 4902,-937.17
  text "COMPONENTS MARKED 'DNP' SHOULD NOT BE POPULATED." at 1156.04,-361.71 h25
  text "ASSEMBLY VARIANT:" at 1155.54,-477.21 h25
  text ".VariantName" at 2191.54,-477.21 h25
  text "PCB VIEWED FROM TOP SIDE" at -228.5,-655.67 h25
  text "BOARD #:" at 2248,-655.67 h25
  text "REV:" at 3638,-655.67 h25
  text ".PCB_Rev" at 3929.5,-655.67 h25
  text "SVN REV:" at 4476,-655.67 h25
  text ".VersionControl_RevNumber" at 4982,-655.67 h25
  text "'.PRJ_Number'" at 2700,-660 h25
  text "TID #:" at 2241,-841.67 h60
  text "Top Assembly" at 589.5,-845.49 h25
  text "00080" at 2693,-846 h50
  text "LAYER NAME =" at -229.5,-858.49 h60
  text "PLOT NAME =" at -228.5,-1064.34 h25
  text ".plot_File_Name" at 577,-1064.34 h25
  text "GENERATED    :" at 2250,-1064.34 h25
  text ".Print_Date" at 3119.5,-1064.34 h25
  text ".Print_Time" at 3848.5,-1064.34 h25
  text "TEXAS INSTRUMENTS" at 5113,-1064.34 h25
M6 Assembly Bottom:
  circle w10: c7104,1582 r6.71
  circle w6: c4373,788 r15.82
  lines w10: -292.5,-727.33 6309.5,-727.33 ; -290.5,-930.67 6309.5,-930.67 ; 1115.5,-1140.5 1115.5,-937.67 ; 1737.5,-727.33 1737.5,-524 ; 2577.5,-727.33 2577.5,-524 ; 3844.5,-1134 3844.5,-524 ; 4733.5,-1134 6309,-1134 6309,-524 -292.5,-524 -292.5,-1134 2304.5,-1134 6309.5,-1134 6309.5,-524
  text "COMPONENTS MARKED 'DNP' SHOULD NOT BE POPULATED." at 6102,-318 h25
  text ".VariantName" at 5058,-434 h25
  text "ASSEMBLY VARIANT:" at 6097,-434 h25
  text ".VersionControl_RevNumber" at 1035.5,-656.17 h25
  text "SVN REV:" at 1541.5,-656.17 h25
  text ".PCB_Rev" at 2088,-656.17 h25
  text "REV:" at 2379.5,-656.17 h25
  text "'.PRJ_Number'" at 3224,-656.17 h25
  text "BOARD #:" at 3769.5,-656.17 h25
  text "PCB VIEWED FROM BOTTOM SIDE" at 6246,-656.17 h25
  text "TID #:" at 3798,-846.67 h60
  text "Bottom Assembly" at 5368,-848 h25
  text "00080" at 3346,-851 h50
  text "LAYER NAME =" at 6237,-864 h60
  text "TEXAS INSTRUMENTS" at 904.5,-1064.84 h25
  text ".Print_Time" at 2169,-1064.84 h25
  text ".Print_Date" at 2898,-1064.84 h25
  text "GENERATED    :" at 3767.5,-1064.84 h25
  text ".plot_File_Name" at 5440.5,-1064.84 h25
  text "PLOT NAME =" at 6246,-1064.84 h25
M7 LPKF Text Top:
  lines w10: 3650,420 3650,2570 ; 4070,335 4070,2440 ; 4170,-125 4170,2435 ; 4840,-120 4840,2445 ; 4940,-130 4940,2435 ; 4940,-50 4940,2515 ; 5040,-60 5040,2505 ; 5710,-170 5710,2440 ; 5710,-145 5710,2435 ; 5710,-35 5710,2530 ; 5810,-85 5810,2480 ; 5810,-45 5810,2520 ; 5910,-95 5910,2470 ; 6380,-165 6380,2440 ; 7028,-165 7028,2430
M9 Title Sheet:
  drawing of 57 lines, arcs and shapes, not listed
  text "1" at 739.84,8036.5 h70
  text "2" at 3235.5,8036.5 h70
  text "3" at 5724.84,8036.5 h70
  text "4" at 8231.51,8036.5 h70
  text "5" at 10730.5,8036.5 h70
  text "6" at 13235.5,8036.5 h70
  text "A" at -416.5,6893.5 h70
  text "A" at 14383.5,6893.5 h70
  text "B" at -416.5,4513.5 h70
  text "B" at 14383.5,4513.5 h70
  text "C" at -416.5,2138.5 h70
  text "C" at 14383.5,2138.5 h70
  text "PROJECT TITLE:" at 11343.5,277.5 h45
  text ".PRJ_Title" at 11393.5,144.17 h70
  text "DESIGNED FOR:" at 11343.5,-23.5 h45
  text ".PRJ_Customer" at 11393.5,-163.5 h70
  text "D" at -416.5,-231.5 h70
  text "D" at 14383.5,-231.5 h70
  text "FILE NAME:" at 11343.5,-323.5 h45
  text ".prj_number" at 11393.5,-443.5 h70
  text "Texas Instruments (TI) and/or its licensors do not warrant the accuracy or completeness of this specification" at 6374,-605.34 h45
  text "ENGINEER:" at 11343.5,-613.5 h45
  text "LAYOUT BY:" at 12848.5,-613.5 h45
  text "or any information contained therein. TI and/or its licensors do not warrant that this design will meet" at 6329.01,-718 h45
  text ".prj_engineer" at 11615,-730 h70
  text "'.PCB_Layout'" at 12948,-735 h70
  text "the specifications, will be suitable for your application or fit for any particular purpose, or will operate in" at 6329.01,-830.67 h45
  text "ALTIUM DESIGNER VERSION:" at 12848.5,-923.5 h45
  text "an implementation. TI and/or its licensors do not warrant that the design is production worthy. You should" at 6329.01,-943.33 h45
  text "completely validate and test your design implementation to confirm the system functionality for your application." at 6374,-1056 h45
  text ".print_Scale" at 11393.5,-1056.83 h70
  text ".Application_BuildNumber" at 12899,-1056.83 h70
  text "1" at 739.84,-1263.5 h70
  text "2" at 3235.5,-1263.5 h70
  text "3" at 5724.84,-1263.5 h70
  text "4" at 8231.51,-1263.5 h70
  text "5" at 10730.5,-1263.5 h70
  text "6" at 13235.5,-1263.5 h70
M10 Fab Notes:
  drawing of 215 lines, arcs and shapes, not listed
  text "DESIGN INFORMATION" at 12381.02,6810 h60
  text "(REFER ALSO ARRAY/PANEL PROFILING INFORMATION)" at 12019.46,6648.29 h60
  text "BOARD SIZE" at 11333.46,6644 h60
  text "185mm" at 11795.78,6516.18 h60
  text "X" at 12301.46,6516.18 h60
  text "65mm" at 12532.78,6516.18 h60
  text "Number of Layers :" at 11736.46,6379 h60
  text "4" at 12831.27,6369 h60
  text "MIN. TRACK WIDTH:" at 11736.46,6240 h60
  text "8" at 12832.7,6240 h60
  text "MIL" at 12987.46,6240 h60
  text "MIN. CLEARANCE:" at 11736.46,6108 h60
  text "8" at 12832.7,6108 h60
  text "MIL" at 12987.46,6108 h60
  text "MIN. VIA PAD SIZE:" at 11736.46,5976 h60
  text "24" at 12802.71,5976 h60
  text "MIL" at 12987.46,5976 h60
  text "0.05mm (2MIL)" at 12431.46,5834.29 h60
  text "MINIMUM ANNULAR RING" at 11407.23,5830 h60
  text "EXTERNAL" at 13139.46,5830 h60
  text "PER" at 11607.23,5712 h60
  text "IPC-D-275 CLASS 2 LEVEL C" at 11827.23,5712 h60
  text "MIL, HOLES" at 13315.46,5599.71 h60
  text "+/-" at 12923,5599 h60
  text "+/-" at 13777,5599 h60
  text "REGISTRATION TOLERANCES:" at 11407.23,5594 h60
  text "METAL" at 12607,5594 h60
  text "5" at 13183.2,5594 h60
  text "3" at 14016.2,5594 h60
  text "MIL" at 14132.46,5594 h60
  text "VIA'S TO BE TENTED" at 11465,5505 h60
  text "MATERIAL:" at 11332.46,5324.54 h60
  text "FR-4 High Tg" at 12318.9,5184.21 h60
  text "FR-408" at 11753.46,5175.64 h60
  text "X" at 12165.46,5175.64 h60
  text "OTHER" at 13241.46,5175.64 h60
  text "63MIL (1.6mm) +/-10%" at 12073.56,5012.92 h60
  text "THICKNESS:" at 11407.23,5008.64 h60
  text "X" at 11945.4,5008.64 h60
  text "OTHER" at 13358.46,5008.64 h60
  text "TOLERANCE:" at 11407.23,4850.64 h60
  text "X" at 12246.53,4850.64 h60
  text "ANSI IPC-6012 TYPE 3 CLASS 2" at 12433.48,4850.64 h60
  text "OTHER +/-" at 12433.46,4694.64 h60
  text "BOW & TWIST:" at 11407.23,4537.64 h60
  text "X" at 12246.53,4537.64 h60
  text "ANSI IPC-6012 TYPE 3 CLASS 2" at 12433.48,4537.64 h60
  text "OTHER +/-" at 12433.46,4379.13 h60
  text "COPPER THICKNESS (FINISHED):" at 11332.46,4243.64 h60
  text "1.4MIL (1oz)" at 12212.46,4090.92 h60
  text "2MIL (1.4oz)" at 12979.46,4090.92 h60
  text "2.8MIL (2oz)" at 13706.46,4090.92 h60
  text "OUTER:" at 11689.46,4086.64 h60
  text "X" at 13580,4080 h60
  text "X" at 12855,3940 h60
  text "1.4MIL (1oz)" at 12212.46,3933.92 h60
  text "2.8MIL (2oz)" at 12979.46,3933.92 h60
  text "N/A" at 13706,3934.29 h60
  text "INNER SIGNAL:" at 11400.38,3929.64 h60
  text "DRILLING:" at 11332.46,3790.64 h60
  text "REFERENCE:" at 11407.23,3673.64 h60
  text "X" at 12055.46,3673.64 h60
  text "AS SHOWN" at 12242.46,3673.64 h60
  text "X" at 12956.46,3673.64 h60
  text "NC_DRILL FILES" at 13093.46,3673.64 h60
  text "PTH MIN COPPER THICKNESS:" at 11407.23,3515.64 h60
  text "X" at 12757.46,3515.64 h60
  text "1MIL" at 12894.46,3515.64 h60
  text "OTHER" at 13391.46,3515.64 h60
  text "BOARD FINISH:" at 11332.46,3356.64 h60
  text "SILKSCREEN:" at 11487.68,3238.64 h60
  text "X" at 12436.46,3238.64 h60
  text "TOP" at 12562.46,3238.64 h60
  text "X" at 12946.46,3238.64 h60
  text "BOTTOM" at 13073.46,3238.64 h60
  text "SILKSCREEN COLOR:" at 11487.68,3071.64 h60
  text "X" at 12435.42,3071.64 h60
  text "WHITE" at 12562.46,3071.64 h60
  text "OTHER" at 13073.46,3071.64 h60
  text "SOLDER RESIST COLOR:" at 11487.68,2901.64 h60
  text "X" at 12055.42,2742.44 h60
  text "GREEN" at 12182.46,2742.44 h60
  text "BLUE" at 12773.46,2742.44 h60
  text "OTHER" at 13311.46,2742.44 h60
  text "IMMERSION GOLD (ENIG)" at 12393.46,2553.92 h60
  text "ENEPIG" at 13731,2550.64 h60
  text "SURFACE FINISH:" at 11332.46,2549.64 h60
  text "X" at 12206.51,2549.64 h60
  text "IMM. TIN/SILVER OR EQUIV" at 11662,2392.64 h60
  text "OTHER" at 13093.46,2392.64 h60
  text "ARRAY/PANEL:" at 11332.46,2213.64 h60
  text "CUT AND TRIM PER MECH LAYER 1" at 12393.46,2209.35 h60
  text "N.C. ROUTE" at 12393.46,2057.64 h60
  text "X" at 13072.46,2057.64 h60
  text "V. SCORE" at 13259.46,2057.64 h60
  text "CERTIFICATION:" at 11332.46,1920.64 h60
  text "MATERIALS AND WORKMANSHIP FOR ALL PCBS" at 12057.46,1920.64 h60
  text "TO MEET OR EXCEED THE REQUIREMENTS OF:" at 12057.46,1822.64 h60
  text "X" at 11683.96,1686.13 h60
  text "ANSI IPC-A-600F CLASS ->" at 11822.96,1686.13 h60
  text "X" at 13462.02,1686.13 h60
  text "2" at 13580.96,1686.14 h60
  text "1" at 13265.96,1684.64 h60
  text "3" at 13934.96,1684.64 h60
  text "X" at 11686.02,1526.64 h60
  text "UL 94V-0" at 11822.96,1526.64 h60
  text "X" at 12498.02,1526.64 h60
  text "RoHS" at 12634.96,1526.64 h60
  text "OTHER" at 13279.36,1526.64 h60
  text "PER ORDER" at 13676.42,1526.64 h60
  text "ADDITIONAL REQUIREMENTS:" at 11332.46,1385.64 h60
  text "MICROSECTION:" at 11407.23,1270.64 h60
  text "YES" at 12312.96,1270.64 h60
  text "REQUIRED" at 13174.46,1114.49 h60
  text "BARE BOARD ELEC. TEST:" at 11407.23,1111.64 h60
  text "NONE" at 12712.96,1111.64 h60
  text "X" at 13047.46,1111.64 h60
  text "PER ORDER" at 13766.46,1111.64 h60
  text "MANUFACTURER'S UL:" at 11407.23,954.64 h60
  text "RAIL" at 12572.96,950.35 h60
  text "METAL" at 13064.77,950.35 h60
  text "X" at 13440,950 h60
  text "SILK" at 13576.46,950.35 h60
M11 Gerber Information:
  lines w10: -292,-930.17 6308,-930.17 ; -292,-726.83 6310,-726.83 ; -292,-523.5 -292,-1133.5 3713,-1133.5 6310,-1133.5 6310,-523.5 -291.5,-523.5 -291.5,-1133.5 1284,-1133.5 ; 2173,-1133.5 2173,-523.5 ; 3440,-726.83 3440,-523.5 ; 4280,-726.83 4280,-523.5 ; 4902,-1140 4902,-937.17
  text ".PRJ_Number" at 2721,-641 h30
  text "ALL ARTWORK VIEWED FROM TOP SIDE" at -228.5,-655.67 h60
  text "BOARD #:" at 2248,-655.67 h60
  text "REV:" at 3638,-655.67 h60
  text ".PCB_Rev" at 3929.5,-655.67 h60
  text "SVN REV:" at 4476,-655.67 h60
  text ".VersionControl_RevNumber" at 4982,-655.67 h60
  text "TID #:" at 2246,-838.67 h60
  text "00080" at 2698,-843 h50
  text "LAYER NAME =" at -228.5,-858.49 h60
  text "PLOT NAME =" at -228.5,-1064.34 h60
  text ".plot_File_Name" at 577,-1064.34 h60
  text "GENERATED    :" at 2250,-1064.34 h60
  text ".Print_Date" at 3119.5,-1064.34 h60
  text ".Print_Time" at 3848.5,-1064.34 h60
  text "TEXAS INSTRUMENTS" at 5113,-1064.34 h60
M12 Stackup:
  lines w6: 11365,7700.5 14240,7700.5 ; 11365,7813.1 14240,7813.1 ; 11305,6976 ccw(c11341,6976) 11341,6940 14264,6940 ccw(c14264,6976) 14300,6976 14300,7914 ccw(c14264,7914) 14264,7950 11341,7950 ccw(c11341,7914) 11305,7914 11305,6976
  text "Layer Stack Up Detail for: TIDA-00080_AMC13x6.PcbDoc" at 11365,7842.95 h52
  text "Layer" at 11365,7771.1 h26
  text "Gerber" at 12371.14,7771.1 h26
  text "Copper" at 13031.52,7771.1 h26
  text "Dielectric" at 13734.35,7771.1 h26
  text "Name" at 11365,7719.1 h26
  text "Document" at 12371.14,7719.1 h26
  text "Thickness" at 13031.52,7719.1 h26
  text "Material" at 13734.35,7719.1 h26
  text "Top Solder Mask" at 11365,7644.9 h36
  text "(.GTS)" at 12371.14,7644.9 h36
  text "Solder Resist" at 13734.35,7644.9 h36
  text "Top Layer" at 11365,7539.69 h36
  text "(.GTL)" at 12371.14,7539.69 h36
  text "2.8mil" at 13031.52,7539.69 h36
  text "FR-4" at 13734.35,7487.08 h36
  text "MidLayer1" at 11365,7434.48 h36
  text "(.G1)" at 12371.14,7434.48 h36
  text "2.8mil" at 13031.52,7434.48 h36
  text "FR-4" at 13734.35,7381.88 h36
  text "MidLayer2" at 11365,7329.27 h36
  text "(.G2)" at 12371.14,7329.27 h36
  text "2.8mil" at 13031.52,7329.27 h36
  text "FR-4" at 13734.35,7276.67 h36
  text "Bottom Layer" at 11365,7224.06 h36
  text "(.GBL)" at 12371.14,7224.06 h36
  text "2.8mil" at 13031.52,7224.06 h36
  text "Bottom Solder Mask" at 11365,7118.85 h36
  text "(.GBS)" at 12371.14,7118.85 h36
  text "Solder Resist" at 13734.35,7118.85 h36
M13 Component Bodies Top:
  text ".Layer_Name" at 577,-858.49 h60
M14 Component Bodies Bottom:
  text ".Layer_Name" at 577,-858.49 h60
M15 Courtyards Top:
  text ".Layer_Name" at 577,-858.49 h60
M16 Courtyards Bottom:
  text ".Layer_Name" at 577,-858.49 h60
Drill Drawing:
  circle w10: c4696.64,5116.28 r33.33
  lines w10: 4663.3,4499.61 4679.97,4499.61 4696.64,4482.95 4713.3,4499.61 4729.97,4499.61 4713.3,4516.28 4729.97,4532.95 4713.3,4532.95 4696.64,4549.61 4679.97,4532.95 4663.3,4532.95 4679.97,4516.28 4663.3,4499.61 ; 4663.3,4632.95 4729.97,4632.95 4729.97,4699.61 4663.3,4699.61 4663.3,4632.95 ; 4663.3,4849.61 4729.97,4849.61 4696.64,4782.95 4663.3,4849.61 ; 4663.3,4932.95 4696.64,4949.61 4729.97,4932.95 4713.3,4966.28 4729.97,4999.61 4696.64,4982.95 4663.3,4999.61 4679.97,4966.28 4663.3,4932.95 ; 4663.3,5249.61 4679.97,5249.61 4679.97,5232.95 4713.3,5232.95 4713.3,5249.61 4729.97,5249.61 4729.97,5282.95 4713.3,5282.95 4713.3,5299.61 4679.97,5299.61 4679.97,5282.95 4663.3,5282.95 4663.3,5249.61 ; 4663.3,5382.95 4663.3,5399.61 4679.97,5416.28 4663.3,5432.95 4663.3,5449.61 4679.97,5449.61 4696.64,5432.95 4713.3,5449.61 4729.97,5449.61 4729.97,5432.95 4713.3,5416.28 4729.97,5399.61 4729.97,5382.95 4713.3,5382.95 4696.64,5399.61 4679.97,5382.95 4663.3,5382.95 ; 4676.64,4646.28 4716.64,4646.28 4716.64,4686.28 4676.64,4686.28 4676.64,4646.28
  lines w15: 4603.51,4437.95 8178.57,4437.95 ; 4603.51,5487.95 8178.57,5487.95 ; 5154.39,4287.95 5154.39,5637.95 ; 5754.23,4287.95 5754.23,5637.95 ; 6893.9,4287.95 6893.9,5637.95 ; 7399.77,4287.95 7399.77,5637.95 ; 4603.51,4287.95 8178.57,4287.95 8178.57,5637.95 4603.51,5637.95 4603.51,4287.95
  text "Drill Table" at 4602.29,5717.8 h60
  text "Symbol" at 4693.51,5532.95 h72
  text "Count" at 5199.39,5532.95 h72
  text "Hole Size" at 5799.23,5532.95 h72
  text "Plated" at 6938.9,5532.95 h72
  text "Hole Type" at 7444.77,5532.95 h72
  text "256" at 5199.39,5382.95 h60
  text "16.00mil (0.406mm)" at 5799.23,5382.95 h60
  text "PTH" at 6938.9,5382.95 h60
  text "Round" at 7444.77,5382.95 h60
  text "8" at 5199.39,5232.95 h60
  text "32.00mil (0.813mm)" at 5799.23,5232.95 h60
  text "PTH" at 6938.9,5232.95 h60
  text "Round" at 7444.77,5232.95 h60
  text "88" at 5199.39,5082.95 h60
  text "38.00mil (0.965mm)" at 5799.23,5082.95 h60
  text "PTH" at 6938.9,5082.95 h60
  text "Round" at 7444.77,5082.95 h60
  text "14" at 5199.39,4932.95 h60
  text "40.00mil (1.016mm)" at 5799.23,4932.95 h60
  text "PTH" at 6938.9,4932.95 h60
  text "Round" at 7444.77,4932.95 h60
  text "FOR 16MIL DRILL +0/-16MIL" at 8403,4840 h60
  text "14" at 5199.39,4782.95 h60
  text "49.21mil (1.250mm)" at 5799.23,4782.95 h60
  text "PTH" at 6938.9,4782.95 h60
  text "Round" at 7444.77,4782.95 h60
  text "FOR PTH DRILL +/-3MIL" at 8403,4722 h60
  text "4" at 5199.39,4632.95 h60
  text "60.00mil (1.524mm)" at 5799.23,4632.95 h60
  text "NPTH" at 6938.9,4632.95 h60
  text "Slot" at 7444.77,4632.95 h60
  text "FOR NPTH DRILL +/-3MIL" at 8404,4606 h60
  text "4" at 5199.39,4482.95 h60
  text "128.00mil (3.251mm)" at 5799.23,4482.95 h60
  text "NPTH" at 6938.9,4482.95 h60
  text "Round" at 7444.77,4482.95 h60
  text "388 Total" at 5199.39,4332.95 h60
  text "Slot definitions :" at 4693.51,4187.97 h60
  text "Routed Path Length" at 5726.2,4187.97 h60
  text "= Calculated from tool start centre position to tool end centre position." at 6828.87,4187.97 h60
  text "Hole Length" at 5726.2,4088 h60
  text "= Routed Path Length + Tool Size = Slot length as defined in the PCB layout" at 6419,4088 h60
  text ".Layer_Name" at 577,-858.49 h60

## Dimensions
0,0 to 0,2559.06 on M2 Board Dimensions
7145.67,2421.26 to 7145.67,137.8 on M2 Board Dimensions
0,2559.06 to 7283.46,2559.06 on M2 Board Dimensions
7145.67,2421.26 to 7283.46,2559.06 on M2 Board Dimensions
7145.67,2421.26 to 7283.46,2559.06 on M2 Board Dimensions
